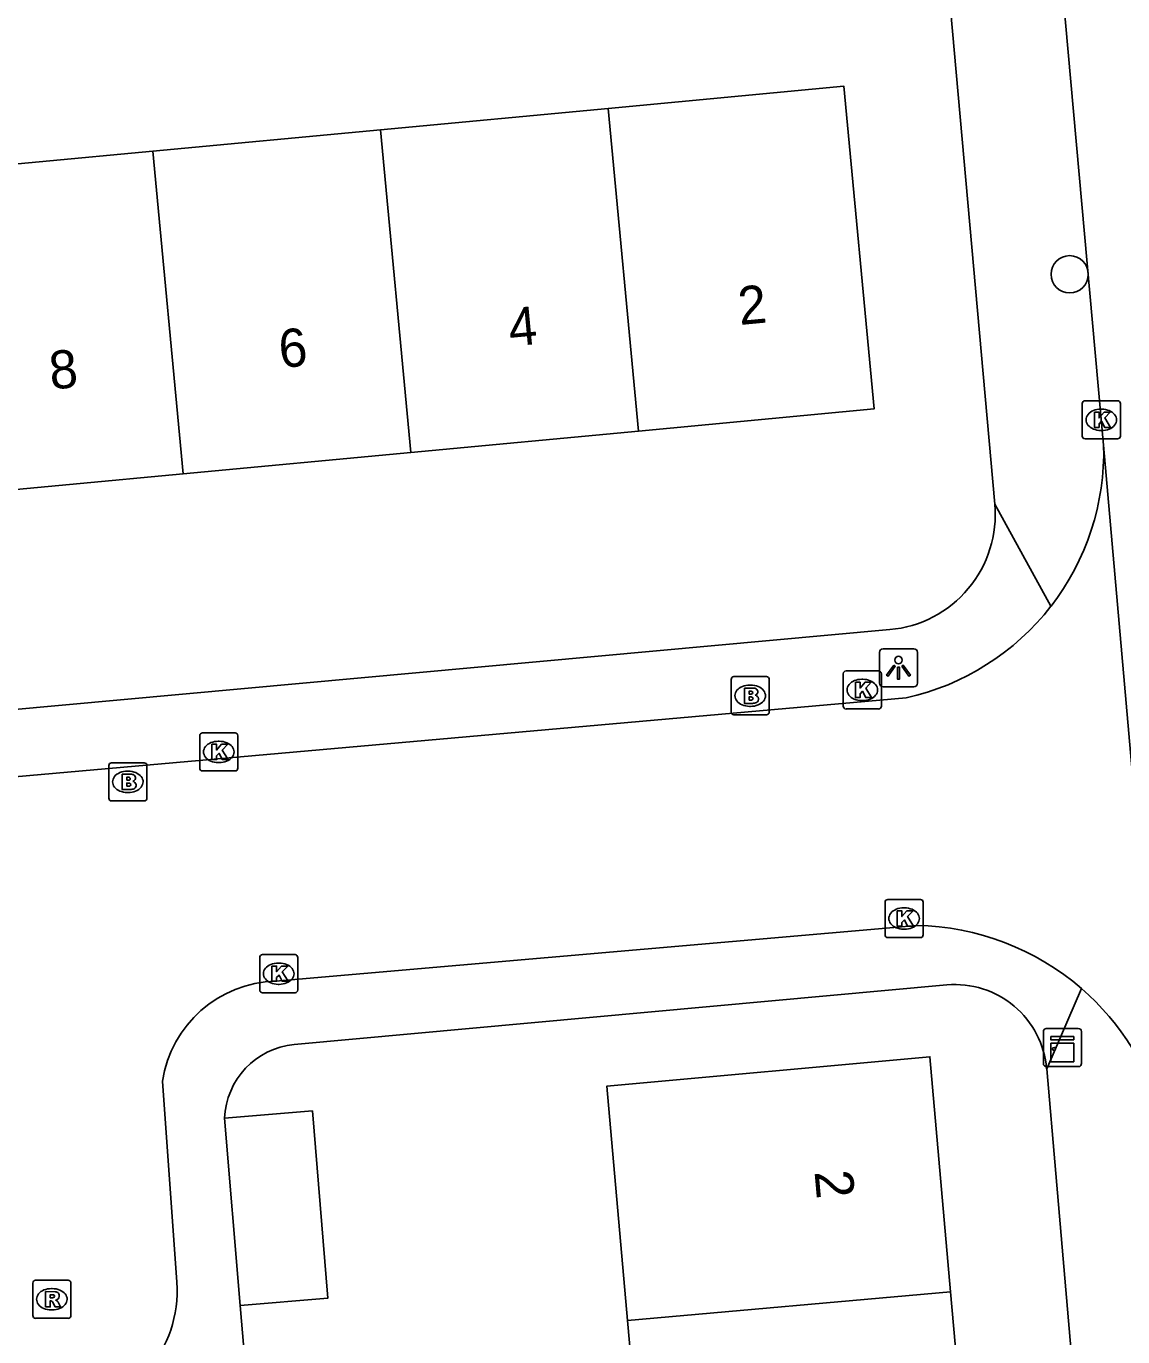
# Model space of a CAD drawing. Extents: x 160557 to 161245, y 385330 to 386505.
# Drawn here: x 160890.27 to 160919.04, y 385534.96 to 385569.34 of the extents above; entities that cross this region are included whole.
import ezdxf

# ---------------------------------------------------------------- set-up
doc = ezdxf.new("R2010")
doc.units = 0
for name, color, linetype in [('IMGEO_Boom', 7, 'Continuous'), ('IMGEO_Brandkraan', 7, 'Continuous'), ('IMGEO_Kast', 7, 'Continuous'), ('IMGEO_Kolk', 7, 'Continuous'), ('IMGEO_Lichtpunt', 7, 'Continuous'), ('IMGEO_Pand', 7, 'Continuous'), ('IMGEO_Pand_nummerreeks', 7, 'Continuous'), ('IMGEO_Rijbaan_lokaal_open', 7, 'Continuous'), ('IMGEO_Rioolput', 7, 'Continuous'), ('IMGEO_Voetpad_open', 7, 'Continuous')]:
    doc.layers.add(name, color=color, linetype=linetype)

msp = doc.modelspace()

# ---------------------------------------------------------------- linework, layer by layer
at = {"layer": 'IMGEO_Boom'}
msp.add_circle((160917.643, 385562.833), 0.489, dxfattribs=at)
at = {"layer": 'IMGEO_Brandkraan'}
for p, q in [((160908.835, 385552.279), (160909.687, 385552.279)), ((160908.76, 385551.353), (160908.76, 385552.205)), ((160909.248, 385552.059), (160909.273, 385552.059)), ((160909.761, 385552.205), (160909.761, 385551.353)), ((160909.687, 385551.279), (160908.835, 385551.279)), ((160909.271, 385551.499), (160909.246, 385551.499)), ((160892.431, 385549.094), (160892.431, 385549.946)), ((160892.506, 385550.02), (160893.358, 385550.02)), ((160893.432, 385549.946), (160893.432, 385549.094)), ((160892.919, 385549.8), (160892.944, 385549.8)), ((160892.942, 385549.24), (160892.917, 385549.24)), ((160893.358, 385549.02), (160892.506, 385549.02))]:
    msp.add_line(p, q, dxfattribs=at)
for points in [[(160908.835, 385552.279), (160909.687, 385552.279)], [(160908.76, 385551.353), (160908.76, 385552.205)], [(160909.108, 385551.979), (160909.108, 385551.579), (160909.321, 385551.579)], [(160909.339, 385551.979), (160909.108, 385551.979)], [(160909.761, 385552.205), (160909.761, 385551.353)], [(160909.287, 385551.898), (160909.233, 385551.898), (160909.233, 385551.822)], [(160909.233, 385551.822), (160909.286, 385551.822)], [(160909.295, 385551.746), (160909.233, 385551.746), (160909.233, 385551.665)], [(160909.233, 385551.665), (160909.295, 385551.665)], [(160909.687, 385551.279), (160908.835, 385551.279)], [(160892.431, 385549.094), (160892.431, 385549.946)], [(160892.506, 385550.02), (160893.358, 385550.02)], [(160893.432, 385549.946), (160893.432, 385549.094)], [(160892.779, 385549.72), (160892.779, 385549.32), (160892.992, 385549.32)], [(160893.01, 385549.72), (160892.779, 385549.72)], [(160892.958, 385549.639), (160892.904, 385549.639), (160892.904, 385549.563)], [(160892.904, 385549.563), (160892.957, 385549.563)], [(160892.966, 385549.487), (160892.904, 385549.487), (160892.904, 385549.406)], [(160892.904, 385549.406), (160892.966, 385549.406)], [(160893.358, 385549.02), (160892.506, 385549.02)]]:
    msp.add_lwpolyline(points, dxfattribs=at)
for centre, radius, start, end in [((160908.837, 385552.203), 0.0765, 91.552, 178.448), ((160908.837, 385552.203), 0.0765, 91.552, 178.448), ((160909.685, 385552.203), 0.0765, 1.552, 88.448), ((160909.685, 385552.203), 0.0765, 1.552, 88.448), ((160909.343, 385551.834), 0.145, 59.4692, 91.5367), ((160909.368, 385551.881), 0.0922, 285.5137, 58.1501), ((160909.288, 385551.86), 0.0379, 267.8285, 90.9355), ((160909.296, 385551.705), 0.0404, 269.8759, 90.5077), ((160909.327, 385551.83), 0.251, 268.6676, 293.5347), ((160909.373, 385551.689), 0.105, 301.3115, 78.989), ((160908.837, 385551.355), 0.0765, 181.552, 268.448), ((160908.837, 385551.355), 0.0765, 181.552, 268.448), ((160909.685, 385551.355), 0.0765, 271.552, 358.448), ((160909.685, 385551.355), 0.0765, 271.552, 358.448), ((160892.508, 385549.944), 0.0765, 91.552, 178.448), ((160892.508, 385549.944), 0.0765, 91.552, 178.448), ((160893.356, 385549.944), 0.0765, 1.552, 88.448), ((160893.356, 385549.944), 0.0765, 1.552, 88.448), ((160892.959, 385549.601), 0.0379, 267.8285, 90.9355), ((160893.014, 385549.575), 0.145, 59.4692, 91.5367), ((160893.039, 385549.622), 0.0922, 285.5137, 58.1501), ((160893.044, 385549.43), 0.105, 301.3115, 78.989), ((160892.967, 385549.446), 0.0404, 269.8759, 90.5077), ((160892.998, 385549.571), 0.251, 268.6676, 293.5347), ((160892.508, 385549.096), 0.0765, 181.552, 268.448), ((160892.508, 385549.096), 0.0765, 181.552, 268.448), ((160893.356, 385549.096), 0.0765, 271.552, 358.448), ((160893.356, 385549.096), 0.0765, 271.552, 358.448)]:
    msp.add_arc(centre, radius, start, end, dxfattribs=at)
for centre, major_axis, ratio, start_param, end_param in [((160909.247, 385551.779), (-0.387, 0.002), 0.722429, 4.712389, 7.853982), ((160909.272, 385551.779), (-0.39, 0.002), 0.717154, 1.570796, 4.712389), ((160892.918, 385549.52), (-0.387, 0.002), 0.722429, 4.712389, 7.853982), ((160892.943, 385549.52), (-0.39, 0.002), 0.717154, 1.570796, 4.712389)]:
    msp.add_ellipse(centre, major_axis=major_axis, ratio=ratio, start_param=start_param, end_param=end_param, dxfattribs=at)
at = {"layer": 'IMGEO_Kast'}
for p, q in [((160917.028, 385543.05), (160917.869, 385543.05)), ((160917.869, 385543.05), (160917.028, 385543.05)), ((160916.953, 385542.125), (160916.953, 385542.966)), ((160916.953, 385542.966), (160916.953, 385542.125)), ((160917.953, 385542.975), (160917.953, 385542.134)), ((160917.953, 385542.134), (160917.953, 385542.975)), ((160917.878, 385542.05), (160917.037, 385542.05)), ((160917.037, 385542.05), (160917.878, 385542.05))]:
    msp.add_line(p, q, dxfattribs=at)
for points in [[(160917.148, 385542.84), (160917.748, 385542.84), (160917.748, 385542.755), (160917.148, 385542.755), (160917.148, 385542.84)], [(160917.148, 385542.665), (160917.748, 385542.665), (160917.748, 385542.176), (160917.148, 385542.176), (160917.148, 385542.665)]]:
    msp.add_lwpolyline(points, dxfattribs=at)
msp.add_circle((160917.232, 385542.514), 0.0377, dxfattribs=at)
for centre, start, end in [((160917.031, 385542.972), 92.4484, 184.2845), ((160917.031, 385542.972), 92.4484, 184.2845), ((160917.875, 385542.972), 2.4484, 94.2845), ((160917.875, 385542.972), 2.4484, 94.2845), ((160917.031, 385542.128), 182.4484, 274.2845), ((160917.031, 385542.128), 182.4484, 274.2845), ((160917.875, 385542.128), 272.4484, 4.2845), ((160917.875, 385542.128), 272.4484, 4.2845)]:
    msp.add_arc(centre, 0.0779, start, end, dxfattribs=at)
at = {"layer": 'IMGEO_Kolk'}
for p, q in [((160918.047, 385559.516), (160918.899, 385559.516)), ((160917.972, 385558.59), (160917.972, 385559.442)), ((160918.46, 385559.296), (160918.485, 385559.296)), ((160918.973, 385559.442), (160918.973, 385558.59)), ((160918.899, 385558.516), (160918.047, 385558.516)), ((160918.483, 385558.736), (160918.458, 385558.736)), ((160911.701, 385551.505), (160911.701, 385552.357)), ((160911.776, 385552.431), (160912.628, 385552.431)), ((160912.702, 385552.357), (160912.702, 385551.505)), ((160912.189, 385552.211), (160912.214, 385552.211)), ((160912.212, 385551.651), (160912.187, 385551.651)), ((160912.628, 385551.431), (160911.776, 385551.431)), ((160894.818, 385549.879), (160894.818, 385550.731)), ((160894.893, 385550.805), (160895.745, 385550.805)), ((160895.306, 385550.585), (160895.331, 385550.585)), ((160895.819, 385550.731), (160895.819, 385549.879)), ((160895.329, 385550.025), (160895.304, 385550.025)), ((160895.745, 385549.805), (160894.893, 385549.805)), ((160912.874, 385546.435), (160913.726, 385546.435)), ((160912.799, 385545.509), (160912.799, 385546.361)), ((160913.287, 385546.215), (160913.312, 385546.215)), ((160913.8, 385546.361), (160913.8, 385545.509)), ((160913.726, 385545.435), (160912.874, 385545.435)), ((160913.31, 385545.655), (160913.285, 385545.655)), ((160896.391, 385544.062), (160896.391, 385544.914)), ((160896.466, 385544.988), (160897.318, 385544.988)), ((160896.879, 385544.768), (160896.904, 385544.768)), ((160897.392, 385544.914), (160897.392, 385544.062)), ((160896.902, 385544.208), (160896.877, 385544.208)), ((160897.318, 385543.988), (160896.466, 385543.988))]:
    msp.add_line(p, q, dxfattribs=at)
for points in [[(160918.047, 385559.516), (160918.899, 385559.516)], [(160917.972, 385558.59), (160917.972, 385559.442)], [(160918.293, 385559.216), (160918.416, 385559.216), (160918.416, 385559.065), (160918.546, 385559.216), (160918.71, 385559.216), (160918.564, 385559.065), (160918.717, 385558.816), (160918.565, 385558.816), (160918.48, 385558.98), (160918.416, 385558.913), (160918.416, 385558.816), (160918.293, 385558.816), (160918.293, 385559.216)], [(160918.973, 385559.442), (160918.973, 385558.59)], [(160918.899, 385558.516), (160918.047, 385558.516)], [(160911.701, 385551.505), (160911.701, 385552.357)], [(160911.776, 385552.431), (160912.628, 385552.431)], [(160912.702, 385552.357), (160912.702, 385551.505)], [(160912.022, 385552.131), (160912.145, 385552.131), (160912.145, 385551.98), (160912.275, 385552.131), (160912.439, 385552.131), (160912.293, 385551.98), (160912.446, 385551.731), (160912.294, 385551.731), (160912.209, 385551.895), (160912.145, 385551.828), (160912.145, 385551.731), (160912.022, 385551.731), (160912.022, 385552.131)], [(160912.628, 385551.431), (160911.776, 385551.431)], [(160894.818, 385549.879), (160894.818, 385550.731)], [(160894.893, 385550.805), (160895.745, 385550.805)], [(160895.819, 385550.731), (160895.819, 385549.879)], [(160895.139, 385550.505), (160895.262, 385550.505), (160895.262, 385550.354), (160895.392, 385550.505), (160895.556, 385550.505), (160895.41, 385550.354), (160895.563, 385550.105), (160895.411, 385550.105), (160895.326, 385550.269), (160895.262, 385550.202), (160895.262, 385550.105), (160895.139, 385550.105), (160895.139, 385550.505)], [(160895.745, 385549.805), (160894.893, 385549.805)], [(160912.874, 385546.435), (160913.726, 385546.435)], [(160912.799, 385545.509), (160912.799, 385546.361)], [(160913.12, 385546.135), (160913.243, 385546.135), (160913.243, 385545.984), (160913.373, 385546.135), (160913.537, 385546.135), (160913.391, 385545.984), (160913.544, 385545.735), (160913.392, 385545.735), (160913.307, 385545.899), (160913.243, 385545.832), (160913.243, 385545.735), (160913.12, 385545.735), (160913.12, 385546.135)], [(160913.8, 385546.361), (160913.8, 385545.509)], [(160913.726, 385545.435), (160912.874, 385545.435)], [(160896.391, 385544.062), (160896.391, 385544.914)], [(160896.466, 385544.988), (160897.318, 385544.988)], [(160897.392, 385544.914), (160897.392, 385544.062)], [(160896.712, 385544.688), (160896.835, 385544.688), (160896.835, 385544.537), (160896.965, 385544.688), (160897.129, 385544.688), (160896.983, 385544.537), (160897.136, 385544.288), (160896.984, 385544.288), (160896.899, 385544.452), (160896.835, 385544.385), (160896.835, 385544.288), (160896.712, 385544.288), (160896.712, 385544.688)], [(160897.318, 385543.988), (160896.466, 385543.988)]]:
    msp.add_lwpolyline(points, dxfattribs=at)
for centre, start, end in [((160918.049, 385559.44), 91.552, 178.448), ((160918.049, 385559.44), 91.552, 178.448), ((160918.897, 385559.44), 1.552, 88.448), ((160918.897, 385559.44), 1.552, 88.448), ((160918.049, 385558.592), 181.552, 268.448), ((160918.049, 385558.592), 181.552, 268.448), ((160918.897, 385558.592), 271.552, 358.448), ((160918.897, 385558.592), 271.552, 358.448), ((160911.778, 385552.355), 91.552, 178.448), ((160911.778, 385552.355), 91.552, 178.448), ((160912.626, 385552.355), 1.552, 88.448), ((160912.626, 385552.355), 1.552, 88.448), ((160911.778, 385551.507), 181.552, 268.448), ((160911.778, 385551.507), 181.552, 268.448), ((160912.626, 385551.507), 271.552, 358.448), ((160912.626, 385551.507), 271.552, 358.448), ((160894.895, 385550.729), 91.552, 178.448), ((160894.895, 385550.729), 91.552, 178.448), ((160895.743, 385550.729), 1.552, 88.448), ((160895.743, 385550.729), 1.552, 88.448), ((160894.895, 385549.881), 181.552, 268.448), ((160894.895, 385549.881), 181.552, 268.448), ((160895.743, 385549.881), 271.552, 358.448), ((160895.743, 385549.881), 271.552, 358.448), ((160912.876, 385546.359), 91.552, 178.448), ((160912.876, 385546.359), 91.552, 178.448), ((160913.724, 385546.359), 1.552, 88.448), ((160913.724, 385546.359), 1.552, 88.448), ((160912.876, 385545.511), 181.552, 268.448), ((160912.876, 385545.511), 181.552, 268.448), ((160913.724, 385545.511), 271.552, 358.448), ((160913.724, 385545.511), 271.552, 358.448), ((160896.468, 385544.912), 91.552, 178.448), ((160896.468, 385544.912), 91.552, 178.448), ((160897.316, 385544.912), 1.552, 88.448), ((160897.316, 385544.912), 1.552, 88.448), ((160896.468, 385544.064), 181.552, 268.448), ((160896.468, 385544.064), 181.552, 268.448), ((160897.316, 385544.064), 271.552, 358.448), ((160897.316, 385544.064), 271.552, 358.448)]:
    msp.add_arc(centre, 0.0765, start, end, dxfattribs=at)
for centre, major_axis, ratio, start_param, end_param in [((160918.459, 385559.016), (-0.387, 0.002), 0.722429, 4.712389, 7.853982), ((160918.484, 385559.016), (-0.39, 0.002), 0.717154, 1.570796, 4.712389), ((160912.188, 385551.931), (-0.387, 0.002), 0.722429, 4.712389, 7.853982), ((160912.213, 385551.931), (-0.39, 0.002), 0.717154, 1.570796, 4.712389), ((160895.305, 385550.305), (-0.387, 0.002), 0.722429, 4.712389, 7.853982), ((160895.33, 385550.305), (-0.39, 0.002), 0.717154, 1.570796, 4.712389), ((160913.286, 385545.935), (-0.387, 0.002), 0.722429, 4.712389, 7.853982), ((160913.311, 385545.935), (-0.39, 0.002), 0.717154, 1.570796, 4.712389), ((160896.878, 385544.488), (-0.387, 0.002), 0.722429, 4.712389, 7.853982), ((160896.903, 385544.488), (-0.39, 0.002), 0.717154, 1.570796, 4.712389)]:
    msp.add_ellipse(centre, major_axis=major_axis, ratio=ratio, start_param=start_param, end_param=end_param, dxfattribs=at)
at = {"layer": 'IMGEO_Lichtpunt'}
for p, q in [((160913.555, 385553.011), (160912.747, 385553.011)), ((160913.555, 385553.011), (160912.747, 385553.011)), ((160912.653, 385552.916), (160912.653, 385552.109)), ((160912.653, 385552.916), (160912.653, 385552.109)), ((160913.649, 385552.109), (160913.649, 385552.916)), ((160913.649, 385552.109), (160913.649, 385552.916)), ((160912.747, 385552.015), (160913.555, 385552.015)), ((160912.747, 385552.015), (160913.555, 385552.015))]:
    msp.add_line(p, q, dxfattribs=at)
for points in [[(160913.027, 385552.58), (160913.066, 385552.552), (160912.878, 385552.29), (160912.84, 385552.317), (160913.027, 385552.58)], [(160913.129, 385552.532), (160913.176, 385552.532), (160913.176, 385552.21), (160913.129, 385552.21), (160913.129, 385552.532)], [(160913.239, 385552.552), (160913.277, 385552.579), (160913.464, 385552.317), (160913.425, 385552.289), (160913.239, 385552.552)]]:
    msp.add_lwpolyline(points, dxfattribs=at)
msp.add_circle((160913.152, 385552.714), 0.0994, dxfattribs=at)
for centre, start, end in [((160912.747, 385552.916), 90, 180), ((160912.747, 385552.916), 90, 180), ((160913.555, 385552.916), 0, 90), ((160913.555, 385552.916), 0, 90), ((160912.747, 385552.109), 180, 270), ((160912.747, 385552.109), 180, 270), ((160913.555, 385552.109), 270, 0), ((160913.555, 385552.109), 270, 360)]:
    msp.add_arc(centre, 0.0946, start, end, dxfattribs=at)
at = {"layer": 'IMGEO_Pand'}
for points in [[(160905.536, 385567.185), (160911.72, 385567.764), (160912.513, 385559.301), (160906.329, 385558.722)], [(160899.562, 385566.625), (160905.536, 385567.185)], [(160906.329, 385558.722), (160905.536, 385567.185)], [(160893.588, 385566.066), (160899.562, 385566.625)], [(160899.562, 385566.625), (160900.355, 385558.162)], [(160887.615, 385565.506), (160893.588, 385566.066)], [(160893.588, 385566.066), (160894.381, 385557.603)], [(160906.329, 385558.722), (160900.355, 385558.162)], [(160900.355, 385558.162), (160894.381, 385557.603)], [(160894.381, 385557.603), (160888.408, 385557.043)], [(160906.043, 385535.394), (160905.5, 385541.541), (160913.975, 385542.309), (160914.52, 385536.143)], [(160895.471, 385540.695), (160897.773, 385540.887), (160898.182, 385535.98), (160895.88, 385535.788)], [(160895.88, 385535.788), (160895.471, 385540.695)], [(160914.52, 385536.143), (160906.043, 385535.394)], [(160914.52, 385536.143), (160915.048, 385530.166)], [(160906.571, 385529.417), (160906.043, 385535.394)]]:
    msp.add_lwpolyline(points, dxfattribs=at)
at = {"layer": 'IMGEO_Rijbaan_lokaal_open'}
for points in [[(160914.387, 385604.81), (160914.572, 385603.534), (160914.741, 385601.627), (160916.313, 385583.041), (160916.536, 385580.505), (160916.636, 385579.396), (160916.744, 385578.2), (160917.103, 385574.214), (160918.533, 385558.353)], [(160918.533, 385558.353), (160920.088, 385540.64)], [(160913.355, 385551.724), (160871.806, 385548.04)], [(160896.809, 385544.291), (160913.629, 385545.756)], [(160894.217, 385536.396), (160893.843, 385541.672)]]:
    msp.add_lwpolyline(points, dxfattribs=at)
for centre, radius, start, end in [((160911.935, 385558.171), 6.601, 322.238, 1.5771), ((160911.935, 385558.168), 6.598, 282.4267, 322.2596), ((160913.502, 385538.955), 6.802, 49.1441, 88.9266), ((160896.891, 385541.209), 3.083, 91.5249, 171.3646), ((160913.5, 385538.961), 6.798, 14.297, 49.1044), ((160891.013, 385536.168), 3.212, 274.8457, 4.0702)]:
    msp.add_arc(centre, radius, start, end, dxfattribs=at)
at = {"layer": 'IMGEO_Rioolput'}
for p, q in [((160890.512, 385536.448), (160891.364, 385536.448)), ((160890.437, 385535.522), (160890.437, 385536.374)), ((160890.925, 385536.228), (160890.95, 385536.228)), ((160891.438, 385536.374), (160891.438, 385535.522)), ((160891.364, 385535.448), (160890.512, 385535.448)), ((160890.948, 385535.668), (160890.923, 385535.668))]:
    msp.add_line(p, q, dxfattribs=at)
for points in [[(160890.512, 385536.448), (160891.364, 385536.448)], [(160890.437, 385535.522), (160890.437, 385536.374)], [(160891.026, 385536.146), (160890.774, 385536.148), (160890.774, 385535.748)], [(160891.438, 385536.374), (160891.438, 385535.522)], [(160890.774, 385535.748), (160890.898, 385535.748), (160890.898, 385535.91), (160890.909, 385535.91)], [(160890.952, 385536.067), (160890.898, 385536.067), (160890.898, 385535.986)], [(160890.898, 385535.986), (160890.95, 385535.986)], [(160890.956, 385535.881), (160891.027, 385535.748), (160891.167, 385535.748), (160891.102, 385535.874)], [(160891.364, 385535.448), (160890.512, 385535.448)]]:
    msp.add_lwpolyline(points, dxfattribs=at)
for centre, radius, start, end in [((160890.514, 385536.372), 0.0765, 91.552, 178.448), ((160890.514, 385536.372), 0.0765, 91.552, 178.448), ((160891.362, 385536.372), 0.0765, 1.552, 88.448), ((160891.362, 385536.372), 0.0765, 1.552, 88.448), ((160891.025, 385536.036), 0.109, 350.3612, 89.416), ((160890.908, 385535.857), 0.0533, 26.0293, 88.6989), ((160890.934, 385536.175), 0.19, 274.7715, 282.9687), ((160890.958, 385535.971), 0.0964, 77.0061, 93.1865), ((160890.972, 385536.028), 0.0378, 276.6634, 79.6772), ((160891.023, 385536.036), 0.112, 277.5842, 350.9817), ((160891.007, 385535.821), 0.108, 29.5134, 73.7905), ((160890.514, 385535.524), 0.0765, 181.552, 268.448), ((160890.514, 385535.524), 0.0765, 181.552, 268.448), ((160891.362, 385535.524), 0.0765, 271.552, 358.448), ((160891.362, 385535.524), 0.0765, 271.552, 358.448)]:
    msp.add_arc(centre, radius, start, end, dxfattribs=at)
for centre, major_axis, ratio, start_param, end_param in [((160890.924, 385535.948), (-0.387, 0.002), 0.722429, 4.712389, 7.853982), ((160890.949, 385535.948), (-0.39, 0.002), 0.717154, 1.570796, 4.712389)]:
    msp.add_ellipse(centre, major_axis=major_axis, ratio=ratio, start_param=start_param, end_param=end_param, dxfattribs=at)
at = {"layer": 'IMGEO_Voetpad_open'}
for points in [[(160915.678, 385556.807), (160914.058, 385574.884), (160913.808, 385577.673)], [(160917.153, 385554.129), (160915.678, 385556.807)], [(160864.993, 385549.134), (160912.922, 385553.512)], [(160914.423, 385544.194), (160897.297, 385542.63)], [(160917.04, 385541.995), (160917.951, 385544.1)], [(160922.169, 385482.49), (160920.66, 385500), (160917.04, 385541.995)], [(160895.88, 385535.788), (160896.095, 385533.221)]]:
    msp.add_lwpolyline(points, dxfattribs=at)
for centre, radius, start, end in [((160912.657, 385556.534), 3.033, 275.0141, 5.1664), ((160914.634, 385541.789), 2.414, 4.8991, 95.0219), ((160897.488, 385540.621), 2.018, 95.4245, 177.8956)]:
    msp.add_arc(centre, radius, start, end, dxfattribs=at)

# ---------------------------------------------------------------- texts
at = {"layer": 'IMGEO_Pand_nummerreeks'}
for s, rotation, p in [('2', 5.3511, (160908.988, 385561.502)), ('4', 5.3511, (160902.964, 385560.938)), ('6', 5.3511, (160896.937, 385560.373)), ('8', 5.3511, (160890.914, 385559.809)), ('2', 275.0475, (160910.948, 385539.295))]:
    msp.add_text(s, height=1, rotation=rotation, dxfattribs=at).set_placement(p)

doc.saveas('drawing.dxf')
